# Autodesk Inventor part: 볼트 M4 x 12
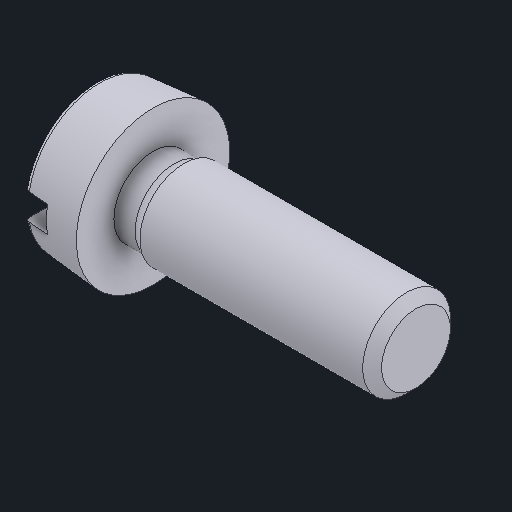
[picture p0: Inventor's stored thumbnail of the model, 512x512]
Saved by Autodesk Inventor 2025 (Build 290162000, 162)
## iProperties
Created: 2025-08
Part Number: 볼트 M4 x 12
Material: 강철, 연강
Description: 6각머리 태핑 나사
Document SubType Name: Modeling
Designer: infra002
Density: 7.85 g/cm^3
Appearance: 기본값
Author: jhkim
Sending System: Autodesk Inventor 2026
Preprocessor: ST-DEVELOPER v20.1
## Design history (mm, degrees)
feature "Solid1"
node "솔리드1"
